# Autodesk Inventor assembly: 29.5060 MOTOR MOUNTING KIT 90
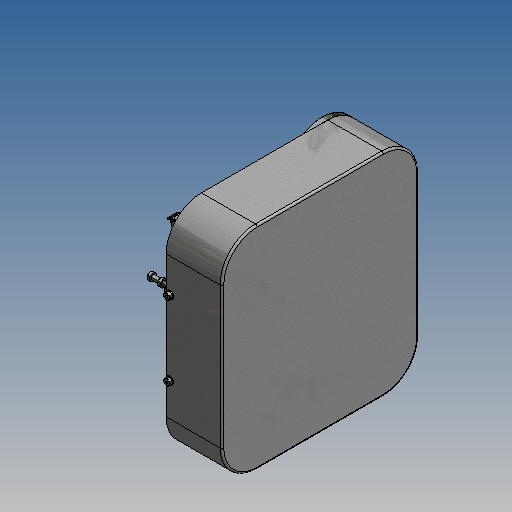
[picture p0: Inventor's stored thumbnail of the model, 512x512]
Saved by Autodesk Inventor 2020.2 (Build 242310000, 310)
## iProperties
Created: 2016-09
Part Number: 29.5060 MOTOR MOUNTING KIT 90
Document SubType Name: Assembly
Designer: Mike Taylor
Mass: 1052.68 g
Surface Area: 5145.29 cm^2
Volume: 1052.68 cm^3
Density: 1 g/cm^3
Author: Mike Taylor
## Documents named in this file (20)
- Y:\INVENTOR LIBRARIES\PARTS LIBRARY\BELT AND ROLLER CONVEYORS\29.5060 MOTOR MOUNTING KIT 90.iam
- Y:\INVENTOR LIBRARIES\PARTS LIBRARY\BELT AND ROLLER CONVEYORS\SUBCOMPONENTS\29.5060 MOTOR MOUNTING KIT 90 SUBCOMPONENTS\29.5060 BALL BEARING.ipt
- Y:\INVENTOR LIBRARIES\PARTS LIBRARY\BELT AND ROLLER CONVEYORS\SUBCOMPONENTS\29.5060 MOTOR MOUNTING KIT 90 SUBCOMPONENTS\29.5060 KEY 6X6X50.ipt
- Y:\INVENTOR LIBRARIES\PARTS LIBRARY\BELT AND ROLLER CONVEYORS\SUBCOMPONENTS\29.5060 MOTOR MOUNTING KIT 90 SUBCOMPONENTS\29.5060 DRIVE SHAFT.ipt
- Y:\INVENTOR LIBRARIES\PARTS LIBRARY\BELT AND ROLLER CONVEYORS\SUBCOMPONENTS\29.5060 MOTOR MOUNTING KIT 90 SUBCOMPONENTS\29.5060 BEARING HOLDER.ipt
- Y:\INVENTOR LIBRARIES\PARTS LIBRARY\BELT AND ROLLER CONVEYORS\SUBCOMPONENTS\29.5060 MOTOR MOUNTING KIT 90 SUBCOMPONENTS\PILOT SPACER 100mm BC.ipt
- Y:\INVENTOR LIBRARIES\PARTS LIBRARY\BELT AND ROLLER CONVEYORS\SUBCOMPONENTS\29.5060 MOTOR MOUNTING KIT 90 SUBCOMPONENTS\29.5060 ALUMINUM PLATE.ipt
- Y:\INVENTOR LIBRARIES\PARTS LIBRARY\BELT AND ROLLER CONVEYORS\SUBCOMPONENTS\29.5060 MOTOR MOUNTING KIT 90 SUBCOMPONENTS\29.5060 COVER.ipt
- Y:\INVENTOR LIBRARIES\PARTS LIBRARY\BELT AND ROLLER CONVEYORS\SUBCOMPONENTS\29.5060 MOTOR MOUNTING KIT 90 SUBCOMPONENTS\29.5063_Pulley_Motor Kit 90.ipt
- Y:\INVENTOR LIBRARIES\PARTS LIBRARY\FASTENING ELEMENTS\WASHERS\21.1127 M8 ROUND WASHER.ipt
- Y:\INVENTOR LIBRARIES\PARTS LIBRARY\FASTENING ELEMENTS\SCREWS CAP\21.1204 M8X25.ipt
- Y:\INVENTOR LIBRARIES\PARTS LIBRARY\FASTENING ELEMENTS\NUTS\21.1351_2 M8 SQUARE NUT POS FXG.ipt
- Y:\INVENTOR LIBRARIES\PARTS LIBRARY\BELT AND ROLLER CONVEYORS\SUBCOMPONENTS\29.5060 MOTOR MOUNTING KIT 90 SUBCOMPONENTS\29.5060 key 6X6X36.ipt
- Y:\INVENTOR LIBRARIES\PARTS LIBRARY\FASTENING ELEMENTS\SCREWS CAP\21.1279 M5X10.ipt
- Y:\INVENTOR LIBRARIES\PARTS LIBRARY\FASTENING ELEMENTS\SCREWS CAP\21.1220 M5X12.ipt
- Y:\INVENTOR LIBRARIES\PARTS LIBRARY\FASTENING ELEMENTS\SET SCREWS\SET SCREW M5X10 POINTED END DIN 914.ipt
- Y:\INVENTOR LIBRARIES\PARTS LIBRARY\BELT AND ROLLER CONVEYORS\SUBCOMPONENTS\29.5060 MOTOR MOUNTING KIT 90 SUBCOMPONENTS\29.5060 TIMING BELT.ipt
- Y:\INVENTOR LIBRARIES\PARTS LIBRARY\FASTENING ELEMENTS\WASHERS\21.1121 M5 ROUND WASHER.ipt
- Y:\INVENTOR LIBRARIES\PARTS LIBRARY\FASTENING ELEMENTS\SCREWS CAP\21.1242 M6X25.ipt
- Y:\INVENTOR LIBRARIES\PARTS LIBRARY\FASTENING ELEMENTS\SCREWS CAP\21.1247 M6X40.ipt
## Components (48 placed, 19 different names)
1. 29.5060 COVER:2 — Flush:6, Mate:11, Mate:12, Insert:44, Insert:45, Insert:46, Insert:47, Flush:12, Flush:13
2. 29.5060 ALUMINUM PLATE:2 — Flush:6, Mate:11, Mate:12, Insert:34, Mate:13, Insert:40, Insert:41, Insert:42, Insert:43, Angle:9, Angle:10, Angle:11, Angle:12, Insert:52, Insert:53, Insert:54, Insert:55, Angle:17, Mate:19, Mate:20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
3. 29.5060 BEARING HOLDER:2 — Insert:34, Mate:13, Insert:35, Insert:36, Insert:37, Insert:38, Insert:39, Mate:15
4. 21.1220 M5 x 12:5 — Insert:37
5. 21.1220 M5 x 12:6 — Insert:38
6. 21.1220 M5 x 12:7 — Insert:36
7. 21.1220 M5 x 12:8 — Insert:35
8. 29.5060 BALL BEARING:2 — Insert:39, Mate:14
9. 21.1351_2 M8 SQUARE NUT POS FXG:5 — Insert:40, Angle:9
10. 21.1351_2 M8 SQUARE NUT POS FXG:6 — Insert:41, Angle:10
11. 21.1351_2 M8 SQUARE NUT POS FXG:7 — Insert:43, Angle:12
12. 21.1351_2 M8 SQUARE NUT POS FXG:8 — Insert:42, Angle:11
13. 21.1121 M5 ROUND WASHER:5 — Insert:44, Insert:49
14. 21.1121 M5 ROUND WASHER:6 — Insert:45, Insert:48
15. 21.1121 M5 ROUND WASHER:7 — Insert:46, Insert:50
16. 21.1121 M5 ROUND WASHER:8 — Insert:47, Insert:51
17. 21.1279 M5 x 10 SHCS:5 — Insert:49
18. 21.1279 M5 x 10 SHCS:6 — Insert:48
19. 21.1279 M5 x 10 SHCS:7 — Insert:50
20. 21.1279 M5 x 10 SHCS:8 — Insert:51
21. 21.1127 WASHER M8:9 — Insert:54, Insert:59
22. 21.1127 WASHER M8:10 — Insert:55, Insert:56
23. 21.1127 WASHER M8:11 — Insert:53, Insert:58
24. 21.1127 WASHER M8:12 — Insert:52, Insert:57
25. 21.1204  M8 x 25:9 — Insert:57
26. 21.1204  M8 x 25:10 — Insert:56
27. 21.1204  M8 x 25:11 — Insert:58
28. 21.1204  M8 x 25:12 — Insert:59
29. 29.5063_Pulley_Motor Kit 90:3 — Mate:14, Angle:17, Mate:15, Mate:16, Tangent:1, Mate:17, Mate:18, Mate:21, Mate:22, Mate:23, Flush:8
30. SET SCREW M5X10 POINTED END DIN 914:3 — Mate:16, Tangent:1
31. 29.5060 TIMING BELT:2 — Mate:17, Mate:18, Mate:25
32. 29.5060 DRIVE SHAFT:2 — Mate:19, Mate:20, Angle:18, Flush:7, Insert:60, Angle:19, Insert:61, Angle:20, Insert:62, Insert:63, Mate:24, Mate:26, Mate:35
33. 29.5060 key 6X6X36:3 — Mate:21, Mate:22, Mate:23
34. 29.5060 key 6X6X36:4 — Insert:60, Angle:19, Angle:21
35. 29.5060 KEY 6X6X50:2 — Insert:61, Angle:20
36. 21.1242 M6 x 25 SHCS:2 — Insert:62
37. 21.1247 M6 x 40:2 — Insert:63
38. 29.5063_Pulley_Motor Kit 90:4 — Angle:21, Mate:24, Flush:8, Mate:25, Mate:33, Mate:34
39. PILOT SPACER 100mm BC:2 — Mate:26, Mate:27, Angle:22, Mate:29, Mate:30, Mate:31, Mate:32
40. 21.1127 WASHER M8:13 — Flush:11, Mate:28, Mate:29, Insert:65
41. 21.1127 WASHER M8:14 — Flush:10, Flush:11, Mate:32, Insert:66
42. 21.1127 WASHER M8:15 — Flush:9, Flush:10, Mate:31, Insert:67
43. 21.1127 WASHER M8:16 — Flush:9, Mate:30, Insert:64
44. 21.1204  M8 x 25:13 — Insert:67
45. 21.1204  M8 x 25:14 — Insert:66
46. 21.1204  M8 x 25:15 — Insert:65
47. 21.1204  M8 x 25:16 — Insert:64
48. SET SCREW M5X10 POINTED END DIN 914:4 — Mate:33, Mate:34
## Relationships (78: Insert 34, Mate 25, Angle 10, Flush 8, Tangent 1)
- Flush:6: 29.5060 COVER:2 ↔ 29.5060 ALUMINUM PLATE:2
- Mate:11: 29.5060 COVER:2 ↔ 29.5060 ALUMINUM PLATE:2
- Mate:12: 29.5060 COVER:2 ↔ 29.5060 ALUMINUM PLATE:2
- Insert:34: 29.5060 ALUMINUM PLATE:2 ↔ 29.5060 BEARING HOLDER:2
- Mate:13: 29.5060 ALUMINUM PLATE:2 ↔ 29.5060 BEARING HOLDER:2
- Insert:35: 29.5060 BEARING HOLDER:2 ↔ 21.1220 M5 x 12:8
- Insert:36: 29.5060 BEARING HOLDER:2 ↔ 21.1220 M5 x 12:7
- Insert:37: 29.5060 BEARING HOLDER:2 ↔ 21.1220 M5 x 12:5
- Insert:38: 29.5060 BEARING HOLDER:2 ↔ 21.1220 M5 x 12:6
- Insert:39: 29.5060 BEARING HOLDER:2 ↔ 29.5060 BALL BEARING:2
- Insert:40: 29.5060 ALUMINUM PLATE:2 ↔ 21.1351_2 M8 SQUARE NUT POS FXG:5
- Insert:41: 29.5060 ALUMINUM PLATE:2 ↔ 21.1351_2 M8 SQUARE NUT POS FXG:6
- Insert:42: 29.5060 ALUMINUM PLATE:2 ↔ 21.1351_2 M8 SQUARE NUT POS FXG:8
- Insert:43: 29.5060 ALUMINUM PLATE:2 ↔ 21.1351_2 M8 SQUARE NUT POS FXG:7
- Insert:44: 29.5060 COVER:2 ↔ 21.1121 M5 ROUND WASHER:5
- Insert:45: 29.5060 COVER:2 ↔ 21.1121 M5 ROUND WASHER:6
- Insert:46: 29.5060 COVER:2 ↔ 21.1121 M5 ROUND WASHER:7
- Insert:47: 29.5060 COVER:2 ↔ 21.1121 M5 ROUND WASHER:8
- Insert:48: 21.1121 M5 ROUND WASHER:6 ↔ 21.1279 M5 x 10 SHCS:6
- Insert:49: 21.1121 M5 ROUND WASHER:5 ↔ 21.1279 M5 x 10 SHCS:5
- Insert:50: 21.1121 M5 ROUND WASHER:7 ↔ 21.1279 M5 x 10 SHCS:7
- Insert:51: 21.1121 M5 ROUND WASHER:8 ↔ 21.1279 M5 x 10 SHCS:8
- Angle:9: 29.5060 ALUMINUM PLATE:2 ↔ 21.1351_2 M8 SQUARE NUT POS FXG:5
- Angle:10: 29.5060 ALUMINUM PLATE:2 ↔ 21.1351_2 M8 SQUARE NUT POS FXG:6
- Angle:11: 29.5060 ALUMINUM PLATE:2 ↔ 21.1351_2 M8 SQUARE NUT POS FXG:8
- Angle:12: 29.5060 ALUMINUM PLATE:2 ↔ 21.1351_2 M8 SQUARE NUT POS FXG:7
- Insert:52: 29.5060 ALUMINUM PLATE:2 ↔ 21.1127 WASHER M8:12
- Insert:53: 29.5060 ALUMINUM PLATE:2 ↔ 21.1127 WASHER M8:11
- Insert:54: 29.5060 ALUMINUM PLATE:2 ↔ 21.1127 WASHER M8:9
- Insert:55: 29.5060 ALUMINUM PLATE:2 ↔ 21.1127 WASHER M8:10
- Insert:56: 21.1127 WASHER M8:10 ↔ 21.1204  M8 x 25:10
- Insert:57: 21.1127 WASHER M8:12 ↔ 21.1204  M8 x 25:9
- Insert:58: 21.1127 WASHER M8:11 ↔ 21.1204  M8 x 25:11
- Insert:59: 21.1127 WASHER M8:9 ↔ 21.1204  M8 x 25:12
- Mate:14: 29.5060 BALL BEARING:2 ↔ 29.5063_Pulley_Motor Kit 90:3
- Angle:17: 29.5060 ALUMINUM PLATE:2 ↔ 29.5063_Pulley_Motor Kit 90:3
- Mate:15: 29.5060 BEARING HOLDER:2 ↔ 29.5063_Pulley_Motor Kit 90:3
- Mate:16: 29.5063_Pulley_Motor Kit 90:3 ↔ SET SCREW M5X10 POINTED END DIN 914:3
- Tangent:1: 29.5063_Pulley_Motor Kit 90:3 ↔ SET SCREW M5X10 POINTED END DIN 914:3
- Mate:17: 29.5063_Pulley_Motor Kit 90:3 ↔ 29.5060 TIMING BELT:2
- Mate:18: 29.5063_Pulley_Motor Kit 90:3 ↔ 29.5060 TIMING BELT:2
- Mate:19: 29.5060 ALUMINUM PLATE:2 ↔ 29.5060 DRIVE SHAFT:2
- Mate:20: 29.5060 ALUMINUM PLATE:2 ↔ 29.5060 DRIVE SHAFT:2
- Angle:18: 29.5060 ALUMINUM PLATE:2 ↔ 29.5060 DRIVE SHAFT:2
- Flush:7: 29.5060 ALUMINUM PLATE:2 ↔ 29.5060 DRIVE SHAFT:2
- Insert:60: 29.5060 DRIVE SHAFT:2 ↔ 29.5060 key 6X6X36:4
- Angle:19: 29.5060 DRIVE SHAFT:2 ↔ 29.5060 key 6X6X36:4
- Insert:61: 29.5060 DRIVE SHAFT:2 ↔ 29.5060 KEY 6X6X50:2
- Angle:20: 29.5060 DRIVE SHAFT:2 ↔ 29.5060 KEY 6X6X50:2
- Insert:62: 29.5060 DRIVE SHAFT:2 ↔ 21.1242 M6 x 25 SHCS:2
- Insert:63: 29.5060 DRIVE SHAFT:2 ↔ 21.1247 M6 x 40:2
- Mate:21: 29.5063_Pulley_Motor Kit 90:3 ↔ 29.5060 key 6X6X36:3
- Mate:22: 29.5063_Pulley_Motor Kit 90:3 ↔ 29.5060 key 6X6X36:3
- Mate:23: 29.5063_Pulley_Motor Kit 90:3 ↔ 29.5060 key 6X6X36:3
- Angle:21: 29.5060 key 6X6X36:4 ↔ 29.5063_Pulley_Motor Kit 90:4
- Mate:24: 29.5060 DRIVE SHAFT:2 ↔ 29.5063_Pulley_Motor Kit 90:4
- Flush:8: 29.5063_Pulley_Motor Kit 90:3 ↔ 29.5063_Pulley_Motor Kit 90:4
- Mate:25: 29.5060 TIMING BELT:2 ↔ 29.5063_Pulley_Motor Kit 90:4
- Mate:26: 29.5060 DRIVE SHAFT:2 ↔ PILOT SPACER 100mm BC:2
- Mate:27: 29.5060 ALUMINUM PLATE:2 ↔ PILOT SPACER 100mm BC:2
- Angle:22: 29.5060 ALUMINUM PLATE:2 ↔ PILOT SPACER 100mm BC:2
- Flush:9: 21.1127 WASHER M8:15 ↔ 21.1127 WASHER M8:16
- Flush:10: 21.1127 WASHER M8:14 ↔ 21.1127 WASHER M8:15
- Flush:11: 21.1127 WASHER M8:13 ↔ 21.1127 WASHER M8:14
- Mate:28: 29.5060 ALUMINUM PLATE:2 ↔ 21.1127 WASHER M8:13
- Mate:29: PILOT SPACER 100mm BC:2 ↔ 21.1127 WASHER M8:13
- Mate:30: PILOT SPACER 100mm BC:2 ↔ 21.1127 WASHER M8:16
- Mate:31: PILOT SPACER 100mm BC:2 ↔ 21.1127 WASHER M8:15
- Mate:32: PILOT SPACER 100mm BC:2 ↔ 21.1127 WASHER M8:14
- Insert:64: 21.1127 WASHER M8:16 ↔ 21.1204  M8 x 25:16
- Insert:65: 21.1127 WASHER M8:13 ↔ 21.1204  M8 x 25:15
- Insert:66: 21.1127 WASHER M8:14 ↔ 21.1204  M8 x 25:14
- Insert:67: 21.1127 WASHER M8:15 ↔ 21.1204  M8 x 25:13
- Mate:33: 29.5063_Pulley_Motor Kit 90:4 ↔ SET SCREW M5X10 POINTED END DIN 914:4
- Mate:34: 29.5063_Pulley_Motor Kit 90:4 ↔ SET SCREW M5X10 POINTED END DIN 914:4
- Flush:12: 29.5060 COVER:2
- Flush:13: 29.5060 COVER:2
- Mate:35: 29.5060 DRIVE SHAFT:2
